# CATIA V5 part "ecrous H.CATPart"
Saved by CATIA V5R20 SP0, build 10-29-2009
Part number: Ecrous H - M30
Material "X2CrNi18-09": density 7900 kg/m3, Young's modulus 0.2 Pa, Poisson ratio 0.19
Bounding box of the stored display mesh (mm): x -23 to 23, y -26.558 to 26.558, z -12.8 to 12.8
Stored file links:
  C:\travail\CAO\bib catia\ecrous\ecrous H.CATPart
  C:\travail\CAO\bib catia\ecrous\ecrou H.xls
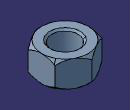
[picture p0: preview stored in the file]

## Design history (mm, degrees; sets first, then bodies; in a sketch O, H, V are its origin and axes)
Parameters
  Designation = "Ecrous H - M30" {design table}
  m = 25.6 mm {design table}
  s = 46 mm {design table}
  p = 3.5 mm {design table}
  d = "M30" {design table}
Body1 (main body)
  Sketch1 on xy-plane, origin (0, 0, 0), H (1, 0, 0), V (0, 1, 0)
    point P1 (23, -13.2791)
    point P2 (23, 13.2791)
    point P3 (0, 26.5581)
    point P4 (-23, 13.2791)
    point P5 (-23, -13.2791)
    point P6 (0, -26.5581)
    point P7 (23, 0)
    construction line L1 (23, -13.2791) -> (23, 13.2791)
    construction line L2 (23, 13.2791) -> (0, 26.5581)
    construction line L3 (0, 26.5581) -> (-23, 13.2791)
    construction line L4 (-23, 13.2791) -> (-23, -13.2791)
    construction line L5 (-23, -13.2791) -> (0, -26.5581)
    construction line L6 (0, -26.5581) -> (23, -13.2791)
    construction line L7 (0, 0) -> (23, 0)
    circle A1 centre (0, 0) radius 26.5581
    construction arc A2 centre (-23, -13.2791) radius 26.5581 from (-23, 13.2791) to (0, -26.5581) cw
    construction arc A3 centre (23, 13.2791) radius 26.5581 from (0, 26.5581) to (23, -13.2791) ccw
    distance L4 L1 = 46 {= s}
    horizontal: L7 H
    coincidence: A1 P1, A1 P2, A1 P3, A1 P4, A1 P5, A1 P6, A2 O, A3 O
    midpoint: P7 L1
  Pad1: profile Sketch1, direction (0, 0, 1), length 12.8 {= m /2}, mirrored extent
  Sketch2 on end face of Pad1, origin (0, 0, 12.8), H (1, 0, 0), V (0, 1, 0)
    point P1 (23, -13.2791)
    point P2 (23, 13.2791)
    point P3 (0, 26.5581)
    point P4 (-23, 13.2791)
    point P5 (-23, -13.2791)
    point P6 (0, -26.5581)
    point P7 (23, 0)
    line L1 (23, -13.2791) -> (23, 13.2791)
    line L2 (23, 13.2791) -> (0, 26.5581)
    line L3 (0, 26.5581) -> (-23, 13.2791)
    line L4 (-23, 13.2791) -> (-23, -13.2791)
    line L5 (-23, -13.2791) -> (0, -26.5581)
    line L6 (0, -26.5581) -> (23, -13.2791)
    construction line L7 (0, 0) -> (23, 0)
    construction circle A1 centre (0, 0) radius 26.5581
    construction arc A2 centre (-23, -13.2791) radius 26.5581 from (-23, 13.2791) to (0, -26.5581) cw
    construction arc A3 centre (23, 13.2791) radius 26.5581 from (0, 26.5581) to (23, -13.2791) ccw
    reference projected circle E1 centre (0, 0) radius 26.5581 from edge [face of Pad1 from Sketch1.A1 | end face of Pad1]
    horizontal: L7 H
    coincidence: A1 P1, A1 P2, A1 P3, A1 P4, A1 P5, A1 P6, A2 O, A3 O, P2 E1
    midpoint: P7 L1
    parallelism: L1 L4
  Sketch3 on zx-plane, origin (0, 0, 0), H (-1, 0, 0), V (0, 0, 1)
    point P1 (-26.5581, 12.8)
    line L1 (-26.5581, 12.8) -> (-26.5581, 9.2419)
    line L2 (-26.5581, 9.2419) -> (-23, 12.8)
    point P3 (-23, 12.8)
    line L3 (-23, 12.8) -> (-26.5581, 12.8)
    reference intersected line E1 (-9.2376, 12.8) -> (9.2376, 12.8) from end face of Pad1
    point P4 (-26.5581, 12.8)
    reference projected point E3 (-23, 12.8) from Sketch2.L1
    axis line L4 (0, 0) -> (0, 13.8114)
    angle L2 L1 = 45
    vertical: L1 V, L4 V
    horizontal: L3 H
    coincidence: L3 E1, P1 P4, P3 E3
  Groove1: profile Sketch3, axis Sketch3.L4, angle 360
  Mirror1: of Groove1, about xy-plane
  Pocket1: profile Sketch2, direction (0, 0, -1), through (limit type 3), outer side
  Sketch4 on end face of Pad1, origin (0, 0, 12.8), H (1, 0, 0), V (0, 1, 0)
    point P1 (0, 0)
  Hole1: placed by Sketch4, at (0, 0, 12.8) direction (0, 0, -1), diameter 26.211, through (limit type 6), threaded "M30", thread diameter 30, thread depth 25.6, pitch 3.5
  Chamfer1: length 1.75 {= p /2}, angle 45, on edge [end face of Pad1 | face of Hole1]; edge [face of Hole1 | start face of Pad1]
Relations
  Hole1.ThreadDescription = d
  design table, configuration 9, drives d, m, s, p, Designation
